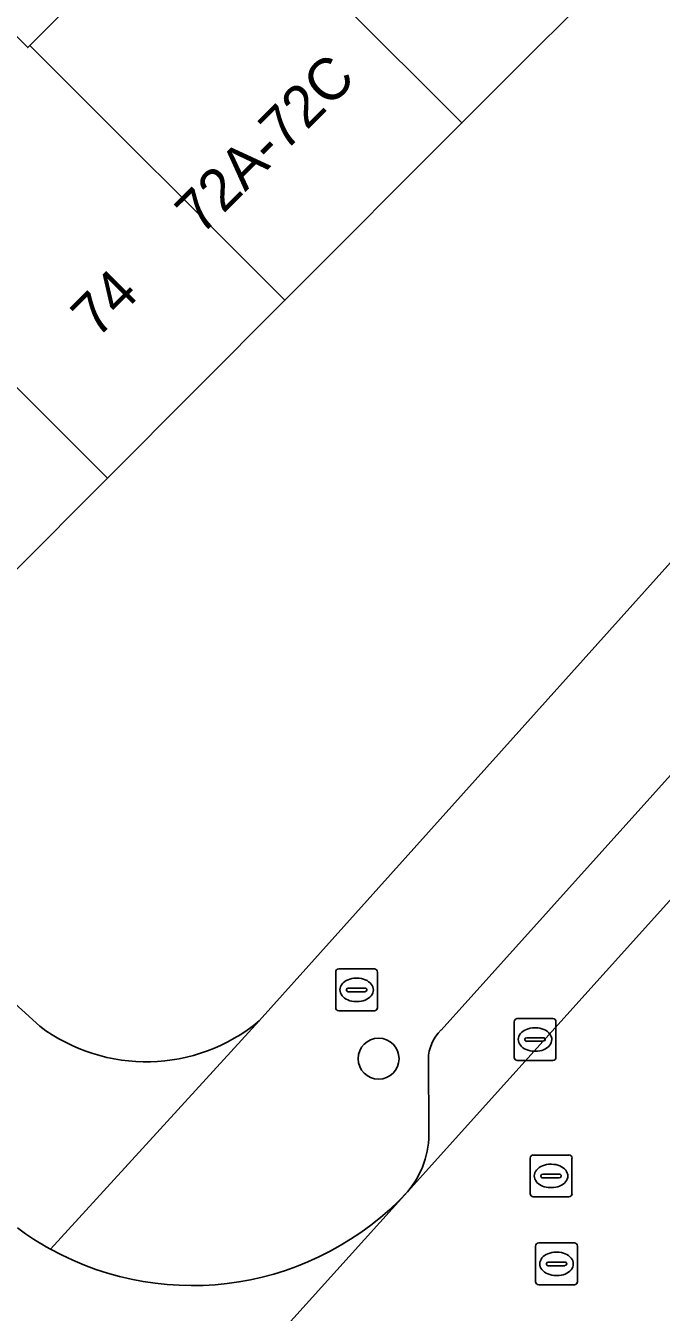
# Model space of a CAD drawing. Extents: x 159039 to 160102, y 381214 to 382524.
# Drawn here: x 159593.38 to 159608.59, y 381776.22 to 381806.97 of the extents above; entities that cross this region are included whole.
import ezdxf

# ---------------------------------------------------------------- set-up
doc = ezdxf.new("R2010")
doc.units = 0
for name, color, linetype in [('IMGEO_Boom', 7, 'Continuous'), ('IMGEO_Brandkraan', 7, 'Continuous'), ('IMGEO_Erf', 7, 'Continuous'), ('IMGEO_Kolk', 7, 'Continuous'), ('IMGEO_Pand', 7, 'Continuous'), ('IMGEO_Pand_nummerreeks', 7, 'Continuous'), ('IMGEO_Parkeervlak_open', 7, 'Continuous'), ('IMGEO_Rijbaan_lokaal_open', 7, 'Continuous'), ('IMGEO_Rioolput', 7, 'Continuous'), ('IMGEO_Voetpad_open', 7, 'Continuous')]:
    doc.layers.add(name, color=color, linetype=linetype)

msp = doc.modelspace()

# ---------------------------------------------------------------- linework, layer by layer
at = {"layer": 'IMGEO_Boom'}
msp.add_circle((159601.824, 381782.28), 0.489, dxfattribs=at)
at = {"layer": 'IMGEO_Brandkraan'}
for p, q in [((159600.798, 381783.498), (159600.798, 381784.35)), ((159600.873, 381784.424), (159601.725, 381784.424)), ((159601.286, 381784.204), (159601.311, 381784.204)), ((159601.799, 381784.35), (159601.799, 381783.498)), ((159601.057, 381783.918), (159601.057, 381783.93)), ((159601.1, 381783.967), (159601.498, 381783.967)), ((159601.541, 381783.93), (159601.541, 381783.918)), ((159601.495, 381783.881), (159601.097, 381783.881)), ((159601.309, 381783.644), (159601.284, 381783.644)), ((159601.725, 381783.424), (159600.873, 381783.424))]:
    msp.add_line(p, q, dxfattribs=at)
for points in [[(159600.798, 381783.498), (159600.798, 381784.35)], [(159600.873, 381784.424), (159601.725, 381784.424)], [(159601.799, 381784.35), (159601.799, 381783.498)], [(159601.725, 381783.424), (159600.873, 381783.424)]]:
    msp.add_lwpolyline(points, dxfattribs=at)
for centre, radius, start, end in [((159600.875, 381784.348), 0.0765, 91.552, 178.448), ((159600.875, 381784.348), 0.0765, 91.552, 178.448), ((159601.723, 381784.348), 0.0765, 1.552, 88.448), ((159601.723, 381784.348), 0.0765, 1.552, 88.448), ((159601.097, 381783.927), 0.0403, 85.8775, 175.7526), ((159601.094, 381783.917), 0.0366, 178.938, 274.7102), ((159601.498, 381783.924), 0.043, 264.8664, 352.4533), ((159601.502, 381783.929), 0.0386, 1.7309, 96.639), ((159600.875, 381783.5), 0.0765, 181.552, 268.448), ((159600.875, 381783.5), 0.0765, 181.552, 268.448), ((159601.723, 381783.5), 0.0765, 271.552, 358.448), ((159601.723, 381783.5), 0.0765, 271.552, 358.448)]:
    msp.add_arc(centre, radius, start, end, dxfattribs=at)
for centre, major_axis, ratio, start_param, end_param in [((159601.285, 381783.924), (-0.387, 0.002), 0.722429, 4.712389, 7.853982), ((159601.31, 381783.924), (-0.39, 0.002), 0.717154, 1.570796, 4.712389)]:
    msp.add_ellipse(centre, major_axis=major_axis, ratio=ratio, start_param=start_param, end_param=end_param, dxfattribs=at)
at = {"layer": 'IMGEO_Erf'}
for points in [[(159598.968, 381783.181), (159640.171, 381829.067), (159659.371, 381850.323)], [(159624.98, 381825.839), (159620.747, 381821.601), (159616.515, 381817.362), (159612.283, 381813.124), (159608.05, 381808.885), (159603.818, 381804.647), (159599.584, 381800.408), (159595.336, 381796.154), (159590.733, 381791.544)], [(159591.325, 381808.555), (159593.431, 381806.451), (159593.482, 381806.502), (159595.146, 381808.169), (159595.45, 381807.865), (159598.019, 381810.438), (159600.602, 381813.025), (159600.351, 381813.276), (159602, 381814.927), (159603.708, 381816.638), (159603.974, 381816.373), (159606.498, 381818.901), (159609.084, 381821.49), (159608.835, 381821.739), (159610.481, 381823.388)], [(159574.268, 381800.68), (159593.719, 381783.056)]]:
    msp.add_lwpolyline(points, dxfattribs=at)
msp.add_arc((159596.264, 381786.437), 4.232, 233.0208, 309.7076, dxfattribs=at)
at = {"layer": 'IMGEO_Kolk'}
for p, q in [((159605.066, 381782.312), (159605.066, 381783.164)), ((159605.141, 381783.238), (159605.993, 381783.238)), ((159605.554, 381783.018), (159605.579, 381783.018)), ((159606.067, 381783.164), (159606.067, 381782.312)), ((159605.325, 381782.732), (159605.325, 381782.744)), ((159605.763, 381782.695), (159605.365, 381782.695)), ((159605.368, 381782.781), (159605.766, 381782.781)), ((159605.809, 381782.744), (159605.809, 381782.732)), ((159605.577, 381782.458), (159605.552, 381782.458)), ((159605.993, 381782.238), (159605.141, 381782.238))]:
    msp.add_line(p, q, dxfattribs=at)
for points in [[(159605.066, 381782.312), (159605.066, 381783.164)], [(159605.141, 381783.238), (159605.993, 381783.238)], [(159606.067, 381783.164), (159606.067, 381782.312)], [(159605.993, 381782.238), (159605.141, 381782.238)]]:
    msp.add_lwpolyline(points, dxfattribs=at)
for centre, radius, start, end in [((159605.143, 381783.162), 0.0765, 91.552, 178.448), ((159605.143, 381783.162), 0.0765, 91.552, 178.448), ((159605.991, 381783.162), 0.0765, 1.552, 88.448), ((159605.991, 381783.162), 0.0765, 1.552, 88.448), ((159605.365, 381782.741), 0.0403, 85.8775, 175.7526), ((159605.362, 381782.731), 0.0366, 178.938, 274.7102), ((159605.766, 381782.738), 0.043, 264.8664, 352.4533), ((159605.77, 381782.743), 0.0386, 1.7309, 96.639), ((159605.143, 381782.314), 0.0765, 181.552, 268.448), ((159605.143, 381782.314), 0.0765, 181.552, 268.448), ((159605.991, 381782.314), 0.0765, 271.552, 358.448), ((159605.991, 381782.314), 0.0765, 271.552, 358.448)]:
    msp.add_arc(centre, radius, start, end, dxfattribs=at)
for centre, major_axis, ratio, start_param, end_param in [((159605.553, 381782.738), (-0.387, 0.002), 0.722429, 4.712389, 7.853982), ((159605.578, 381782.738), (-0.39, 0.002), 0.717154, 1.570796, 4.712389)]:
    msp.add_ellipse(centre, major_axis=major_axis, ratio=ratio, start_param=start_param, end_param=end_param, dxfattribs=at)
at = {"layer": 'IMGEO_Pand'}
for points in [[(159603.818, 381804.647), (159608.05, 381808.885), (159602, 381814.927), (159600.351, 381813.276), (159600.602, 381813.025), (159598.019, 381810.438)], [(159599.584, 381800.408), (159603.818, 381804.647), (159598.019, 381810.438), (159595.45, 381807.865), (159595.146, 381808.169), (159593.482, 381806.502)], [(159593.482, 381806.502), (159593.431, 381806.451), (159591.325, 381808.555), (159589.697, 381806.924), (159591.803, 381804.821), (159592.127, 381804.499), (159589.556, 381801.925), (159595.336, 381796.154), (159599.584, 381800.408)], [(159589.556, 381801.925), (159587.767, 381803.711), (159586.974, 381802.917), (159585.997, 381801.939), (159586.893, 381801.005), (159587.42, 381800.479), (159584.862, 381797.919), (159585.004, 381797.778), (159582.519, 381795.117), (159585.749, 381792.071), (159587.973, 381794.299), (159590.733, 381791.544), (159595.336, 381796.154)]]:
    msp.add_lwpolyline(points, close=True, dxfattribs=at)
at = {"layer": 'IMGEO_Parkeervlak_open'}
for points in [[(159624.86, 381806.887), (159603.32, 381782.965)], [(159602.517, 381779.098), (159626.352, 381805.552)], [(159603.015, 381782.266), (159603.026, 381780.56)]]:
    msp.add_lwpolyline(points, dxfattribs=at)
for centre, radius, start, end in [((159604.011, 381782.248), 0.996, 133.9126, 178.9405), ((159600.853, 381780.497), 2.174, 319.9451, 1.6634)]:
    msp.add_arc(centre, radius, start, end, dxfattribs=at)
at = {"layer": 'IMGEO_Rijbaan_lokaal_open'}
for points in [[(159613.786, 381785.161), (159629.549, 381802.659), (159626.352, 381805.552), (159602.517, 381779.098), (159591.852, 381767.299), (159591.512, 381766.925), (159538.424, 381708.169), (159529.21, 381698.27), (159532.297, 381695.293), (159544.91, 381708.807), (159546.267, 381710.129)], [(159591.852, 381767.299), (159602.517, 381779.098)]]:
    msp.add_lwpolyline(points, dxfattribs=at)
for centre, radius, start, end in [((159597.366, 381783.895), 7.039, 241.1963, 317.0381), ((159597.33, 381783.836), 6.97, 233.5015, 241.2188)]:
    msp.add_arc(centre, radius, start, end, dxfattribs=at)
at = {"layer": 'IMGEO_Rioolput'}
for p, q in [((159605.45, 381779.051), (159605.45, 381779.903)), ((159605.525, 381779.977), (159606.377, 381779.977)), ((159606.451, 381779.903), (159606.451, 381779.051)), ((159605.938, 381779.757), (159605.963, 381779.757)), ((159605.709, 381779.471), (159605.709, 381779.483)), ((159606.147, 381779.434), (159605.749, 381779.434)), ((159605.752, 381779.52), (159606.15, 381779.52)), ((159606.193, 381779.483), (159606.193, 381779.471)), ((159606.377, 381778.977), (159605.525, 381778.977)), ((159605.961, 381779.197), (159605.936, 381779.197)), ((159605.581, 381776.949), (159605.581, 381777.801)), ((159605.656, 381777.875), (159606.508, 381777.875)), ((159606.582, 381777.801), (159606.582, 381776.949)), ((159606.069, 381777.655), (159606.094, 381777.655)), ((159605.84, 381777.369), (159605.84, 381777.381)), ((159606.278, 381777.332), (159605.88, 381777.332)), ((159605.883, 381777.418), (159606.281, 381777.418)), ((159606.324, 381777.381), (159606.324, 381777.369)), ((159606.508, 381776.875), (159605.656, 381776.875)), ((159606.092, 381777.095), (159606.067, 381777.095))]:
    msp.add_line(p, q, dxfattribs=at)
for points in [[(159605.45, 381779.051), (159605.45, 381779.903)], [(159605.525, 381779.977), (159606.377, 381779.977)], [(159606.451, 381779.903), (159606.451, 381779.051)], [(159606.377, 381778.977), (159605.525, 381778.977)], [(159605.581, 381776.949), (159605.581, 381777.801)], [(159605.656, 381777.875), (159606.508, 381777.875)], [(159606.582, 381777.801), (159606.582, 381776.949)], [(159606.508, 381776.875), (159605.656, 381776.875)]]:
    msp.add_lwpolyline(points, dxfattribs=at)
for centre, radius, start, end in [((159605.527, 381779.901), 0.0765, 91.552, 178.448), ((159605.527, 381779.901), 0.0765, 91.552, 178.448), ((159606.375, 381779.901), 0.0765, 1.552, 88.448), ((159606.375, 381779.901), 0.0765, 1.552, 88.448), ((159605.749, 381779.48), 0.0403, 85.8775, 175.7526), ((159605.746, 381779.47), 0.0366, 178.938, 274.7102), ((159606.15, 381779.477), 0.043, 264.8664, 352.4533), ((159606.154, 381779.482), 0.0386, 1.7309, 96.639), ((159605.527, 381779.053), 0.0765, 181.552, 268.448), ((159605.527, 381779.053), 0.0765, 181.552, 268.448), ((159606.375, 381779.053), 0.0765, 271.552, 358.448), ((159606.375, 381779.053), 0.0765, 271.552, 358.448), ((159605.658, 381777.799), 0.0765, 91.552, 178.448), ((159605.658, 381777.799), 0.0765, 91.552, 178.448), ((159606.506, 381777.799), 0.0765, 1.552, 88.448), ((159606.506, 381777.799), 0.0765, 1.552, 88.448), ((159605.88, 381777.378), 0.0403, 85.8775, 175.7526), ((159605.877, 381777.368), 0.0366, 178.938, 274.7102), ((159606.281, 381777.375), 0.043, 264.8664, 352.4533), ((159606.285, 381777.38), 0.0386, 1.7309, 96.639), ((159605.658, 381776.951), 0.0765, 181.552, 268.448), ((159605.658, 381776.951), 0.0765, 181.552, 268.448), ((159606.506, 381776.951), 0.0765, 271.552, 358.448), ((159606.506, 381776.951), 0.0765, 271.552, 358.448)]:
    msp.add_arc(centre, radius, start, end, dxfattribs=at)
for centre, major_axis, ratio, start_param, end_param in [((159605.937, 381779.477), (-0.387, 0.002), 0.722429, 4.712389, 7.853982), ((159605.962, 381779.477), (-0.39, 0.002), 0.717154, 1.570796, 4.712389), ((159606.068, 381777.375), (-0.387, 0.002), 0.722429, 4.712389, 7.853982), ((159606.093, 381777.375), (-0.39, 0.002), 0.717154, 1.570796, 4.712389)]:
    msp.add_ellipse(centre, major_axis=major_axis, ratio=ratio, start_param=start_param, end_param=end_param, dxfattribs=at)
at = {"layer": 'IMGEO_Voetpad_open'}
for points in [[(159659.371, 381850.323), (159640.171, 381829.067), (159598.968, 381783.181), (159593.974, 381777.727)], [(159603.32, 381782.965), (159624.86, 381806.887), (159637.437, 381820.824), (159659.663, 381845.532)], [(159593.719, 381783.056), (159574.268, 381800.68)], [(159593.974, 381777.727), (159598.968, 381783.181)], [(159603.026, 381780.56), (159603.015, 381782.266)]]:
    msp.add_lwpolyline(points, dxfattribs=at)
for centre, radius, start, end in [((159596.264, 381786.437), 4.232, 233.0208, 309.7076), ((159604.011, 381782.248), 0.996, 133.9126, 178.9405), ((159600.853, 381780.497), 2.174, 319.9451, 1.6634), ((159597.366, 381783.895), 7.039, 241.1963, 317.0381), ((159597.33, 381783.836), 6.97, 233.5015, 241.2188)]:
    msp.add_arc(centre, radius, start, end, dxfattribs=at)

# ---------------------------------------------------------------- texts
at = {"layer": 'IMGEO_Pand_nummerreeks'}
for s, rotation, p in [('72A-72C', 44.9229, (159597.579, 381801.94)), ('74', 45.0402, (159595.086, 381799.469))]:
    msp.add_text(s, height=1, rotation=rotation, dxfattribs=at).set_placement(p)

doc.saveas('drawing.dxf')
